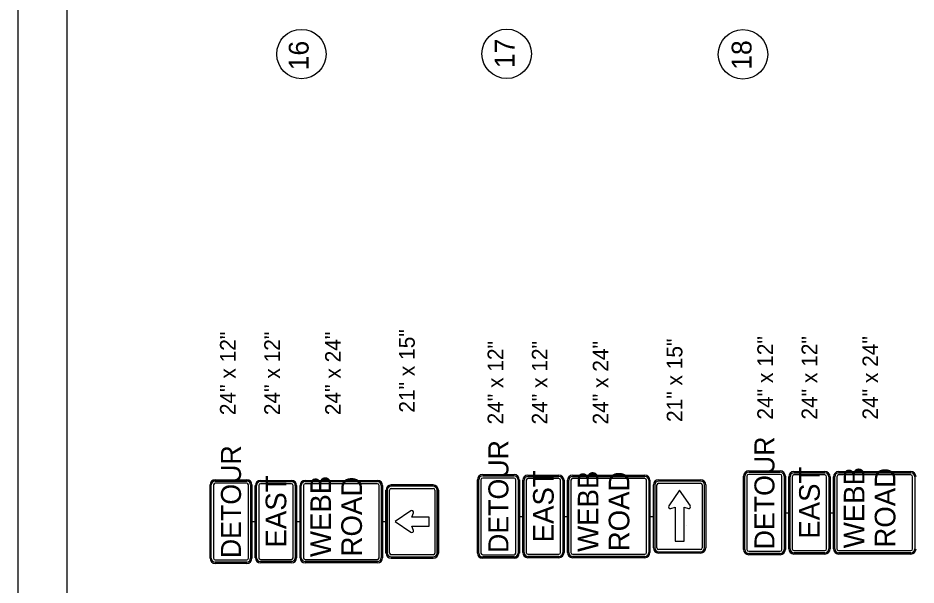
# Model space of a CAD drawing. Extents: x 1149904 to 1171904, y 589308 to 623636.
# Drawn here: x 1149904 to 1156977, y 597473 to 601940 of the extents above; entities that cross this region are included whole.
import ezdxf

# ---------------------------------------------------------------- set-up
doc = ezdxf.new("R2010")
doc.units = 0
for name, color, linetype in [('BORDER', 7, 'Continuous'), ('D_Text_Standard', 7, 'Continuous'), ('PLOT BOUNDARY', 7, 'Continuous'), ('SIGNS TRAFFIC', 7, 'Continuous')]:
    doc.layers.add(name, color=color, linetype=linetype)

msp = doc.modelspace()

# ---------------------------------------------------------------- linework, layer by layer
at = {"layer": 'BORDER'}
msp.add_lwpolyline([(1150292.4, 590926.2), (1150292.4, 622926.2), (1171292.4, 622926.2), (1171292.4, 590926.2)], close=True, dxfattribs=at)
at = {"layer": 'D_Text_Standard'}
for p, q in [((1153852.9, 598013.3), (1153879.9, 598013.3)), ((1154204.9, 598013.3), (1154231.9, 598013.3)), ((1154881.9, 598013.3), (1154908.9, 598013.3)), ((1155948.1, 598041.8), (1155975.1, 598041.8)), ((1156300.1, 598041.8), (1156327.1, 598041.8)), ((1151746.7, 597972.5), (1151773.7, 597972.5)), ((1152098.7, 597972.5), (1152125.7, 597972.5)), ((1152775.7, 597972.5), (1152802.7, 597972.5))]:
    msp.add_line(p, q, dxfattribs=at)
for centre in [(1152136.7, 601655.8), (1153753.3, 601657.3), (1155614.1, 601653.3)]:
    msp.add_circle(centre, 194.5, dxfattribs=at)
at = {"layer": 'PLOT BOUNDARY'}
msp.add_lwpolyline([(1171904.3, 589307.6), (1171904.3, 623307.6), (1149904.3, 623307.6), (1149904.3, 589307.6)], close=True, dxfattribs=at)
at = {"layer": 'SIGNS TRAFFIC'}
for p, q in [((1152813.1, 598220), (1152813.1, 597725)), ((1154919.2, 598260.8), (1154919.2, 597765.8)), ((1155045.3, 598076.2), (1155079, 598087.1)), ((1155079, 598087.1), (1155079, 597817.3)), ((1155151.2, 597817.3), (1155151.2, 598087.1)), ((1155151.2, 598087.1), (1155185, 598076.2)), ((1153007.4, 598008.6), (1153018.2, 598042.3)), ((1153143, 598008.6), (1153007.4, 598008.6)), ((1153143, 597936.4), (1153143, 598008.6)), ((1153018.2, 597902.6), (1153007.4, 597936.4)), ((1153007.4, 597936.4), (1153143, 597936.4)), ((1155079, 597817.3), (1155151.2, 597817.3))]:
    msp.add_line(p, q, dxfattribs=at)
for points in [[(1155659.4, 598371.8), (1155906.9, 598371.8)], [(1155659.4, 598371.8), (1155906.9, 598371.8)], [(1155659.4, 598361.5), (1155906.9, 598361.5)], [(1156015.7, 598366.8), (1156259.5, 598366.8)], [(1156015.7, 598366.8), (1156259.5, 598366.8)], [(1156367.7, 598366.8), (1156936.5, 598366.8)], [(1156367.7, 598366.8), (1156936.5, 598366.8)], [(1151458, 598302.5), (1151705.5, 598302.5)], [(1151458, 598302.5), (1151705.5, 598302.5)], [(1151458, 598292.2), (1151705.5, 598292.2)], [(1151814.4, 598297.5), (1152058.1, 598297.5)], [(1151814.4, 598297.5), (1152058.1, 598297.5)], [(1152166.4, 598297.5), (1152735.1, 598297.5)], [(1152166.4, 598297.5), (1152735.1, 598297.5)], [(1153522.9, 597724.5), (1153522.9, 598302)], [(1153522.9, 597724.5), (1153522.9, 598302)], [(1153533.2, 597724.5), (1153533.2, 598302)], [(1153550.4, 598302), (1153550.4, 597724.5)], [(1153564.1, 598343.3), (1153811.6, 598343.3)], [(1153564.1, 598343.3), (1153811.6, 598343.3)], [(1153564.1, 598332.9), (1153811.6, 598332.9)], [(1153811.6, 598315.8), (1153564.1, 598315.8)], [(1153825.3, 597724.5), (1153825.3, 598302)], [(1153842.5, 598302), (1153842.5, 597724.5)], [(1153852.9, 598302), (1153852.9, 597724.5)], [(1153852.9, 598302), (1153852.9, 597724.5)], [(1153879.9, 597728.9), (1153879.9, 598297.6)], [(1153879.9, 597728.9), (1153879.9, 598297.6)], [(1153890, 597728.9), (1153890, 598297.6)], [(1153907, 598297.6), (1153907, 597728.9)], [(1153920.5, 598338.3), (1154164.2, 598338.3)], [(1153920.5, 598338.3), (1154164.2, 598338.3)], [(1153920.5, 598328.1), (1154164.2, 598328.1)], [(1154164.2, 598311.2), (1153920.5, 598311.2)], [(1154177.8, 597728.9), (1154177.8, 598297.6)], [(1154194.7, 598297.6), (1154194.7, 597728.9)], [(1154204.9, 598297.6), (1154204.9, 597728.9)], [(1154204.9, 598297.6), (1154204.9, 597728.9)], [(1154231.9, 597728.9), (1154231.9, 598297.6)], [(1154231.9, 597728.9), (1154231.9, 598297.6)], [(1154242, 597728.9), (1154242, 598297.6)], [(1154259, 598297.6), (1154259, 597728.9)], [(1154272.5, 598338.3), (1154841.2, 598338.3)], [(1154272.5, 598338.3), (1154841.2, 598338.3)], [(1154272.5, 598328.1), (1154841.2, 598328.1)], [(1154841.2, 598311.2), (1154272.5, 598311.2)], [(1154854.8, 597728.9), (1154854.8, 598297.6)], [(1154871.7, 598297.6), (1154871.7, 597728.9)], [(1154881.9, 598297.6), (1154881.9, 597728.9)], [(1154881.9, 598297.6), (1154881.9, 597728.9)], [(1154950.1, 598302), (1155280.1, 598302)], [(1155280.1, 598291.7), (1154950.1, 598291.7)], [(1155618.1, 597753.1), (1155618.1, 598330.6)], [(1155618.1, 597753.1), (1155618.1, 598330.6)], [(1155628.4, 597753.1), (1155628.4, 598330.6)], [(1155645.6, 598330.6), (1155645.6, 597753.1)], [(1155906.9, 598344.3), (1155659.4, 598344.3)], [(1155920.6, 597753.1), (1155920.6, 598330.6)], [(1155937.8, 598330.6), (1155937.8, 597753.1)], [(1155948.1, 598330.6), (1155948.1, 597753.1)], [(1155948.1, 598330.6), (1155948.1, 597753.1)], [(1155975.1, 597757.5), (1155975.1, 598326.2)], [(1155975.1, 597757.5), (1155975.1, 598326.2)], [(1155985.3, 597757.5), (1155985.3, 598326.2)], [(1156002.2, 598326.2), (1156002.2, 597757.5)], [(1156015.7, 598356.7), (1156259.5, 598356.7)], [(1156259.5, 598339.7), (1156015.7, 598339.7)], [(1156273, 597757.5), (1156273, 598326.2)], [(1156289.9, 598326.2), (1156289.9, 597757.5)], [(1156300.1, 598326.2), (1156300.1, 597757.5)], [(1156300.1, 598326.2), (1156300.1, 597757.5)], [(1156327.1, 597757.5), (1156327.1, 598326.2)], [(1156327.1, 597757.5), (1156327.1, 598326.2)], [(1156337.3, 597757.5), (1156337.3, 598326.2)], [(1156354.2, 598326.2), (1156354.2, 597757.5)], [(1156367.7, 598356.7), (1156936.5, 598356.7)], [(1156936.5, 598339.7), (1156367.7, 598339.7)], [(1156950, 597757.5), (1156950, 598326.2)], [(1156966.9, 598326.2), (1156966.9, 597757.5)], [(1151416.7, 597683.7), (1151416.7, 598261.2)], [(1151416.7, 597683.7), (1151416.7, 598261.2)], [(1151427.1, 597683.7), (1151427.1, 598261.2)], [(1151444.3, 598261.2), (1151444.3, 597683.7)], [(1151705.5, 598275), (1151458, 598275)], [(1151719.2, 597683.7), (1151719.2, 598261.2)], [(1151736.4, 598261.2), (1151736.4, 597683.7)], [(1151746.7, 598261.2), (1151746.7, 597683.7)], [(1151746.7, 598261.2), (1151746.7, 597683.7)], [(1151773.7, 597688.1), (1151773.7, 598256.9)], [(1151773.7, 597688.1), (1151773.7, 598256.9)], [(1151783.9, 597688.1), (1151783.9, 598256.9)], [(1151800.8, 598256.9), (1151800.8, 597688.1)], [(1151814.4, 598287.3), (1152058.1, 598287.3)], [(1152058.1, 598270.4), (1151814.4, 598270.4)], [(1152071.6, 597688.1), (1152071.6, 598256.9)], [(1152088.6, 598256.9), (1152088.6, 597688.1)], [(1152098.7, 598256.9), (1152098.7, 597688.1)], [(1152098.7, 598256.9), (1152098.7, 597688.1)], [(1152125.7, 597688.1), (1152125.7, 598256.9)], [(1152125.7, 597688.1), (1152125.7, 598256.9)], [(1152135.9, 597688.1), (1152135.9, 598256.9)], [(1152152.8, 598256.9), (1152152.8, 597688.1)], [(1152166.4, 598287.3), (1152735.1, 598287.3)], [(1152735.1, 598270.4), (1152166.4, 598270.4)], [(1152748.6, 597688.1), (1152748.6, 598256.9)], [(1152765.6, 598256.9), (1152765.6, 597688.1)], [(1152775.7, 598256.9), (1152775.7, 597688.1)], [(1152775.7, 598256.9), (1152775.7, 597688.1)], [(1152802.7, 597725), (1152802.7, 598220)], [(1152802.7, 598220), (1152802.7, 597725)], [(1152830.3, 597725), (1152830.3, 598220)], [(1152844, 598261.2), (1153174, 598261.2)], [(1153174, 598261.2), (1152844, 598261.2)], [(1153174, 598250.9), (1152844, 598250.9)], [(1152844, 598233.7), (1153174, 598233.7)], [(1153187.7, 598220), (1153187.7, 597725)], [(1153204.9, 597725), (1153204.9, 598220)], [(1153215.2, 598220), (1153215.2, 597725)], [(1153215.2, 597725), (1153215.2, 598220)], [(1154908.9, 597765.8), (1154908.9, 598260.8)], [(1154936.4, 597765.8), (1154936.4, 598260.8)], [(1154950.1, 598274.5), (1155280.1, 598274.5)], [(1155293.8, 598260.8), (1155293.8, 597765.8)], [(1155311, 597765.8), (1155311, 598260.8)], [(1155321.4, 598260.8), (1155321.4, 597765.8)], [(1155199.6, 598095.8), (1155115.1, 598219.5), (1155030.6, 598095.8)], [(1152998.6, 598056.9), (1152874.9, 597972.5), (1152998.6, 597888)], [(1155172.9, 597943.2), (1155172.9, 597943.3)], [(1155280.1, 597752), (1154950.1, 597752)], [(1154950.1, 597734.9), (1155280.1, 597734.9)], [(1155280.1, 597724.5), (1154950.1, 597724.5)], [(1155659.4, 597739.3), (1155906.9, 597739.3)], [(1156015.7, 597743.9), (1156259.5, 597743.9)], [(1156259.5, 597727), (1156015.7, 597727)], [(1156367.7, 597743.9), (1156936.5, 597743.9)], [(1156936.5, 597727), (1156367.7, 597727)], [(1151458, 597670), (1151705.5, 597670)], [(1151814.4, 597674.6), (1152058.1, 597674.6)], [(1152058.1, 597657.7), (1151814.4, 597657.7)], [(1152166.4, 597674.6), (1152735.1, 597674.6)], [(1152735.1, 597657.6), (1152166.4, 597657.6)], [(1153174, 597711.3), (1152844, 597711.3)], [(1152844, 597694.1), (1153174, 597694.1)], [(1153174, 597683.7), (1152844, 597683.7)], [(1152844, 597683.7), (1153174, 597683.7)], [(1153564.1, 597710.8), (1153811.6, 597710.8)], [(1153811.6, 597693.6), (1153564.1, 597693.6)], [(1153811.6, 597683.3), (1153564.1, 597683.3)], [(1153811.6, 597683.3), (1153564.1, 597683.3)], [(1153920.5, 597715.4), (1154164.2, 597715.4)], [(1154164.2, 597698.4), (1153920.5, 597698.4)], [(1154164.2, 597688.3), (1153920.5, 597688.3)], [(1154164.2, 597688.3), (1153920.5, 597688.3)], [(1154272.5, 597715.4), (1154841.2, 597715.4)], [(1154841.2, 597698.4), (1154272.5, 597698.4)], [(1154841.2, 597688.3), (1154272.5, 597688.3)], [(1154841.2, 597688.3), (1154272.5, 597688.3)], [(1155906.9, 597722.2), (1155659.4, 597722.2)], [(1155906.9, 597711.8), (1155659.4, 597711.8)], [(1155906.9, 597711.8), (1155659.4, 597711.8)], [(1156259.5, 597716.8), (1156015.7, 597716.8)], [(1156259.5, 597716.8), (1156015.7, 597716.8)], [(1156936.5, 597716.8), (1156367.7, 597716.8)], [(1156936.5, 597716.8), (1156367.7, 597716.8)], [(1151705.5, 597652.8), (1151458, 597652.8)], [(1151705.5, 597642.5), (1151458, 597642.5)], [(1151705.5, 597642.5), (1151458, 597642.5)], [(1152058.1, 597647.5), (1151814.4, 597647.5)], [(1152058.1, 597647.5), (1151814.4, 597647.5)], [(1152735.1, 597647.5), (1152166.4, 597647.5)], [(1152735.1, 597647.5), (1152166.4, 597647.5)]]:
    msp.add_lwpolyline(points, dxfattribs=at)
for centre, radius, start, end in [((1155659.4, 598330.6), 41.2, 90, 180), ((1155659.4, 598330.6), 41.2, 90, 180), ((1155659.4, 598330.6), 30.9, 90, 180), ((1155906.9, 598330.6), 41.2, 360, 90), ((1155906.9, 598330.6), 41.2, 360, 90), ((1155906.9, 598330.6), 30.9, 360, 90), ((1156015.7, 598326.2), 40.6, 90, 180), ((1156015.7, 598326.2), 40.6, 90, 180), ((1156259.5, 598326.2), 40.6, 360, 90), ((1156259.5, 598326.2), 40.6, 360, 90), ((1156367.7, 598326.2), 40.6, 90, 180), ((1156367.7, 598326.2), 40.6, 90, 180), ((1156936.5, 598326.2), 40.6, 360, 90), ((1156936.5, 598326.2), 40.6, 360, 90), ((1151458, 598261.2), 41.2, 90, 180), ((1151458, 598261.2), 41.2, 90, 180), ((1151458, 598261.2), 30.9, 90, 180), ((1151705.5, 598261.2), 41.2, 360, 90), ((1151705.5, 598261.2), 41.2, 360, 90), ((1151705.5, 598261.2), 30.9, 360, 90), ((1151814.4, 598256.9), 40.6, 90, 180), ((1151814.4, 598256.9), 40.6, 90, 180), ((1152058.1, 598256.9), 40.6, 360, 90), ((1152058.1, 598256.9), 40.6, 360, 90), ((1152166.4, 598256.9), 40.6, 90, 180), ((1152166.4, 598256.9), 40.6, 90, 180), ((1152735.1, 598256.9), 40.6, 360, 90), ((1152735.1, 598256.9), 40.6, 360, 90), ((1153564.1, 598302), 41.2, 90, 180), ((1153564.1, 598302), 41.2, 90, 180), ((1153564.1, 598302), 30.9, 90, 180), ((1153564.1, 598302), 13.7, 90, 180), ((1153811.6, 598302), 41.2, 360, 90), ((1153811.6, 598302), 41.2, 360, 90), ((1153811.6, 598302), 30.9, 360, 90), ((1153811.6, 598302), 13.7, 360, 90), ((1153920.5, 598297.6), 40.6, 90, 180), ((1153920.5, 598297.6), 40.6, 90, 180), ((1153920.5, 598297.6), 30.5, 90, 180), ((1153920.5, 598297.6), 13.5, 90, 180), ((1154164.2, 598297.6), 40.6, 360, 90), ((1154164.2, 598297.6), 40.6, 360, 90), ((1154164.2, 598297.6), 30.5, 360, 90), ((1154164.2, 598297.6), 13.5, 360, 90), ((1154272.5, 598297.6), 40.6, 90, 180), ((1154272.5, 598297.6), 40.6, 90, 180), ((1154272.5, 598297.6), 30.5, 90, 180), ((1154272.5, 598297.6), 13.5, 90, 180), ((1154841.2, 598297.6), 40.6, 360, 90), ((1154841.2, 598297.6), 40.6, 360, 90), ((1154841.2, 598297.6), 30.5, 360, 90), ((1154841.2, 598297.6), 13.5, 360, 90), ((1154950.1, 598260.8), 41.2, 90, 180), ((1154950.1, 598260.8), 30.9, 90, 180), ((1155280.1, 598260.8), 41.2, 360, 90), ((1155280.1, 598260.8), 30.9, 360, 90), ((1155659.4, 598330.6), 13.7, 90, 180), ((1155906.9, 598330.6), 13.7, 360, 90), ((1156015.7, 598326.2), 30.5, 90, 180), ((1156015.7, 598326.2), 13.5, 90, 180), ((1156259.5, 598326.2), 30.5, 360, 90), ((1156259.5, 598326.2), 13.5, 360, 90), ((1156367.7, 598326.2), 30.5, 90, 180), ((1156367.7, 598326.2), 13.5, 90, 180), ((1156936.5, 598326.2), 30.5, 360, 90), ((1156936.5, 598326.2), 13.5, 360, 90), ((1151458, 598261.2), 13.7, 90, 180), ((1151705.5, 598261.2), 13.7, 360, 90), ((1151814.4, 598256.9), 30.5, 90, 180), ((1151814.4, 598256.9), 13.5, 90, 180), ((1152058.1, 598256.9), 30.5, 360, 90), ((1152058.1, 598256.9), 13.5, 360, 90), ((1152166.4, 598256.9), 30.5, 90, 180), ((1152166.4, 598256.9), 13.5, 90, 180), ((1152735.1, 598256.9), 30.5, 360, 90), ((1152735.1, 598256.9), 13.5, 360, 90), ((1152844, 598220), 41.2, 90, 180), ((1152844, 598220), 41.2, 90, 180), ((1152844, 598220), 30.9, 90, 180), ((1152844, 598220), 13.7, 90, 180), ((1153174, 598220), 41.2, 360, 90), ((1153174, 598220), 41.2, 360, 90), ((1153174, 598220), 30.9, 360, 90), ((1153174, 598220), 13.7, 360, 90), ((1154950.1, 598260.8), 13.7, 90, 180), ((1155280.1, 598260.8), 13.7, 360, 90), ((1155041.3, 598088.5), 12.9, 145.67628, 287.81281), ((1155188.9, 598088.5), 12.9, 252.18716, 34.32372), ((1153005.9, 598046.3), 12.9, 342.18716, 124.32372), ((1153005.9, 597898.7), 12.9, 235.67628, 17.81281), ((1152844, 597725), 41.2, 180, 270), ((1152844, 597725), 41.2, 180, 270), ((1152844, 597725), 30.9, 180, 270), ((1152844, 597725), 13.7, 180, 270), ((1153174, 597725), 41.2, 270, 0), ((1153174, 597725), 41.2, 270, 0), ((1153174, 597725), 30.9, 270, 0), ((1153174, 597725), 13.7, 270, 0), ((1153564.1, 597724.5), 41.2, 180, 270), ((1153564.1, 597724.5), 41.2, 180, 270), ((1153564.1, 597724.5), 30.9, 180, 270), ((1153564.1, 597724.5), 13.7, 180, 270), ((1153811.6, 597724.5), 41.2, 270, 360), ((1153811.6, 597724.5), 41.2, 270, 360), ((1153811.6, 597724.5), 30.9, 270, 360), ((1153811.6, 597724.5), 13.7, 270, 360), ((1153920.5, 597728.9), 40.6, 180, 270), ((1153920.5, 597728.9), 40.6, 180, 270), ((1153920.5, 597728.9), 30.5, 180, 270), ((1153920.5, 597728.9), 13.5, 180, 270), ((1154164.2, 597728.9), 40.6, 270, 360), ((1154164.2, 597728.9), 40.6, 270, 360), ((1154164.2, 597728.9), 30.5, 270, 360), ((1154164.2, 597728.9), 13.5, 270, 360), ((1154272.5, 597728.9), 40.6, 180, 270), ((1154272.5, 597728.9), 40.6, 180, 270), ((1154272.5, 597728.9), 30.5, 180, 270), ((1154272.5, 597728.9), 13.5, 180, 270), ((1154841.2, 597728.9), 40.6, 270, 360), ((1154841.2, 597728.9), 40.6, 270, 360), ((1154841.2, 597728.9), 30.5, 270, 360), ((1154841.2, 597728.9), 13.5, 270, 360), ((1154950.1, 597765.8), 41.2, 180, 270), ((1154950.1, 597765.8), 30.9, 180, 270), ((1154950.1, 597765.8), 13.7, 180, 270), ((1155280.1, 597765.8), 41.2, 270, 0), ((1155280.1, 597765.8), 30.9, 270, 0), ((1155280.1, 597765.8), 13.7, 270, 0), ((1155659.4, 597753.1), 41.2, 180, 270), ((1155659.4, 597753.1), 41.2, 180, 270), ((1155659.4, 597753.1), 30.9, 180, 270), ((1155659.4, 597753.1), 13.7, 180, 270), ((1155906.9, 597753.1), 41.2, 270, 360), ((1155906.9, 597753.1), 41.2, 270, 360), ((1155906.9, 597753.1), 30.9, 270, 360), ((1155906.9, 597753.1), 13.7, 270, 360), ((1156015.7, 597757.5), 40.6, 180, 270), ((1156015.7, 597757.5), 40.6, 180, 270), ((1156015.7, 597757.5), 30.5, 180, 270), ((1156015.7, 597757.5), 13.5, 180, 270), ((1156259.5, 597757.5), 40.6, 270, 360), ((1156259.5, 597757.5), 40.6, 270, 360), ((1156259.5, 597757.5), 30.5, 270, 360), ((1156259.5, 597757.5), 13.5, 270, 360), ((1156367.7, 597757.5), 40.6, 180, 270), ((1156367.7, 597757.5), 40.6, 180, 270), ((1156367.7, 597757.5), 30.5, 180, 270), ((1156367.7, 597757.5), 13.5, 180, 270), ((1156936.5, 597757.5), 40.6, 270, 360), ((1156936.5, 597757.5), 40.6, 270, 360), ((1156936.5, 597757.5), 30.5, 270, 360), ((1156936.5, 597757.5), 13.5, 270, 360), ((1151458, 597683.7), 41.2, 180, 270), ((1151458, 597683.7), 41.2, 180, 270), ((1151458, 597683.7), 30.9, 180, 270), ((1151458, 597683.7), 13.7, 180, 270), ((1151705.5, 597683.7), 41.2, 270, 360), ((1151705.5, 597683.7), 41.2, 270, 360), ((1151705.5, 597683.7), 30.9, 270, 360), ((1151705.5, 597683.7), 13.7, 270, 360), ((1151814.4, 597688.1), 40.6, 180, 270), ((1151814.4, 597688.1), 40.6, 180, 270), ((1151814.4, 597688.1), 30.5, 180, 270), ((1151814.4, 597688.1), 13.5, 180, 270), ((1152058.1, 597688.1), 40.6, 270, 360), ((1152058.1, 597688.1), 40.6, 270, 360), ((1152058.1, 597688.1), 30.5, 270, 360), ((1152058.1, 597688.1), 13.5, 270, 360), ((1152166.4, 597688.1), 40.6, 180, 270), ((1152166.4, 597688.1), 40.6, 180, 270), ((1152166.4, 597688.1), 30.5, 180, 270), ((1152166.4, 597688.1), 13.5, 180, 270), ((1152735.1, 597688.1), 40.6, 270, 360), ((1152735.1, 597688.1), 40.6, 270, 360), ((1152735.1, 597688.1), 30.5, 270, 360), ((1152735.1, 597688.1), 13.5, 270, 360)]:
    msp.add_arc(centre, radius, start, end, dxfattribs=at)

# ---------------------------------------------------------------- texts
at = {"layer": 'D_Text_Standard'}
for s, height, p in [('17', 156.21, (1153815.4, 601544.6)), ('16', 156.21, (1152193.4, 601527.5)), ('18', 156.21, (1155681.4, 601531.9)), ('24" x 12"', 123.19, (1151618.6, 598811)), ('24" x 12"', 123.19, (1151967.1, 598811)), ('24" x 24"', 123.19, (1152446.8, 598811)), ('21" x 15"', 123.19, (1153029.4, 598830.4)), ('24" x 12"', 123.19, (1155850.3, 598776.1)), ('24" x 12"', 123.19, (1156198.8, 598776.1)), ('24" x 24"', 123.19, (1156678.5, 598776.1)), ('24" x 12"', 123.19, (1153726, 598737.5)), ('24" x 12"', 123.19, (1154074.6, 598737.5)), ('24" x 24"', 123.19, (1154554.3, 598737.5)), ('21" x 15"', 123.19, (1155136.9, 598757))]:
    msp.add_text(s, height=height, rotation=90, dxfattribs=at).set_placement(p)
at = {"layer": 'SIGNS TRAFFIC'}
for s, height, p in [('DETOUR', 157.5, (1153766.6, 597725.2)), ('DETOUR', 157.5, (1155861.9, 597753.7)), ('DETOUR', 157.5, (1151660.5, 597684.4)), ('EAST', 162.5, (1154123.6, 597809)), ('WEBB', 162.5, (1154475.6, 597733.9)), ('EAST', 162.5, (1156218.9, 597837.5)), ('WEBB', 162.5, (1156570.8, 597762.5)), ('ROAD', 162.5, (1156814.6, 597767.4)), ('EAST', 162.5, (1152017.5, 597768.2)), ('WEBB', 162.5, (1152369.5, 597693.2)), ('ROAD', 162.5, (1152613.2, 597698)), ('ROAD', 162.5, (1154719.3, 597738.8))]:
    msp.add_text(s, height=height, rotation=90, dxfattribs=at).set_placement(p)

doc.saveas('drawing.dxf')
